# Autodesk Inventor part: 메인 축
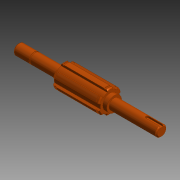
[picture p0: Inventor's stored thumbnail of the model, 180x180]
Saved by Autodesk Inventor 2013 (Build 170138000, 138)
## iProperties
Created: 2015-11
Part Number: 메인 축
Document SubType Name: 모델링
Designer: mdu
Mass: 166.714 g
Surface Area: 71.568 cm^2
Volume: 21.2105 cm^3
Density: 7.86 g/cm^3
Material: 강철, 연강
변환 표준: STEP AP214IS
파일 이름: C:\Users\SeoGD\Desktop\?쒗뿕\硫붿씤 異?.stp
전처리기: Build: 253, Release: 2010 SP1 - Date: Wed 07/29/2009
전송 단위: 밀리미터
불확실성: 0.01
Author: mdu
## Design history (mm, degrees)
sketch "스케치1"
  geometry: L1 (-68, 0)-(68, 0); L2 (68, 0)-(68, 5); L3 (68, 5)-(53, 5); L4 (53, 5)-(53, 4.8); L5 (53, 4.8)-(51.85, 4.8); L6 (51.85, 4.8)-(51.85, 5); L7 (51.85, 5)-(25, 5); L8 (25, 5)-(25, 9); L9 (25, 9)-(-19, 9); L10 (-19, 9)-(-19, 7); L11 (-19, 7)-(-23, 7); L12 (-23, 7)-(-23, 5); L13 (-23, 5)-(-68, 5); L14 (-68, 5)-(-68, 0); 2 further points
  constraints: 28 end point, 9 parallel, 4 collinear, 2 perpendicular, 1 coincident, 1 horizontal, 1 midpoint
  dimensions: "d2" = 1.15 distance between parallel lines of L6 L4; "d3" = 10 diameter of L3 L1; "d4" = 9.6 diameter of L5 L1; "d6" = 44 distance between parallel lines of L10 L8; "d7" = 4 distance between parallel lines of L12 L10; "d8" = 14 diameter of L11 L1; "d9" = 18 diameter of L9 L1; "d33" = 45 distance from line of L12.end L14; "d37" = 43 distance between parallel lines of L8 L2; "d40" = 15 distance between parallel lines of L2 L4
revolve "회전1" sketch "스케치1" stored, may be unused: angle "d10" = 90 deg
sketch "스케치2"
  geometry: L1 (2.5, 10.712)-(2.5, 8.646); L2 (-2.5, 10.712)-(-2.5, 8.646); A1 r 9 centre (0, 0) between (2.5, 8.646) and (-2.5, 8.646) reference; A2 r 11 centre (0, 0) between (2.5, 10.712) and (-2.5, 10.712); 1 further point
  constraints: 4 end point, 4 point on circle, 2 parallel, 1 centre point, 1 coincident, 1 vertical
  dimensions: "d11" = 22 diameter of A2; "d12" = 5 distance between parallel lines of L1 L2
extrude "돌출1" join sketch "스케치2" stored distance "d13" = 10; taper "d14" = 0 deg
chamfer "모따기1" distance "d15" = 1; stored, may be unused: second distance "d16" = 2, angle "d17" = 45 deg
node "작업 평면1"
node "작업 평면2"
sketch "스케치3"
  geometry: L1 (2.5, 10.712)-(2.5, 10.198); L2 (-2.5, 10.712)-(-2.5, 10.198); A1 r 11 centre (0, 0) between (2.5, 10.712) and (-2.5, 10.712) reference; A2 r 10.5 centre (0, 0) between (2.5, 10.198) and (-2.5, 10.198); 1 further point
  constraints: 4 end point, 2 point on circle, 1 centre point, 1 coincident, 1 parallel, 1 vertical
  dimensions: "d19" = 21 diameter of A2
extrude "돌출2" cut sketch "스케치3" distance "d20" = 1.35; taper "d21" = 0 deg
node "작업 평면3"
sketch "스케치4"
  geometry: L1 (-22.5, -5)-(-22.5, 5) reference; L2 (-22.5, 1.5)-(-9, 1.5); L3 (-9, -1.5)-(-22.5, -1.5); A1 r 1.5 centre (-9, 0) between (-9, -1.5) and (-9, 1.5); 2 further points
  constraints: 4 end point, 2 perpendicular, 2 point on circle, 2 point on line, 2 tangent, 1 centre point, 1 horizontal alignment, 1 midpoint
  dimensions: "d25" = 3 distance between parallel lines of L3 L2; "d26" = 15 dimension on A1 L1
extrude "돌출3" cut sketch "스케치4" distance "d27" = 1.8; taper "d28" = 0 deg
chamfer "모따기2" distance "d29" = 1; stored, may be unused: second distance "d30" = 2, angle "d31" = 45 deg
node "솔리드1"
node "솔리드 본체"
node "곡면 본체"
mirror "대칭1"
pattern_circular "원형 패턴1" dims "d23" = 360 deg
node "솔리드2"
other parameters: "d18" = -1.65
